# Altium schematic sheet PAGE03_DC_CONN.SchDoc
size B
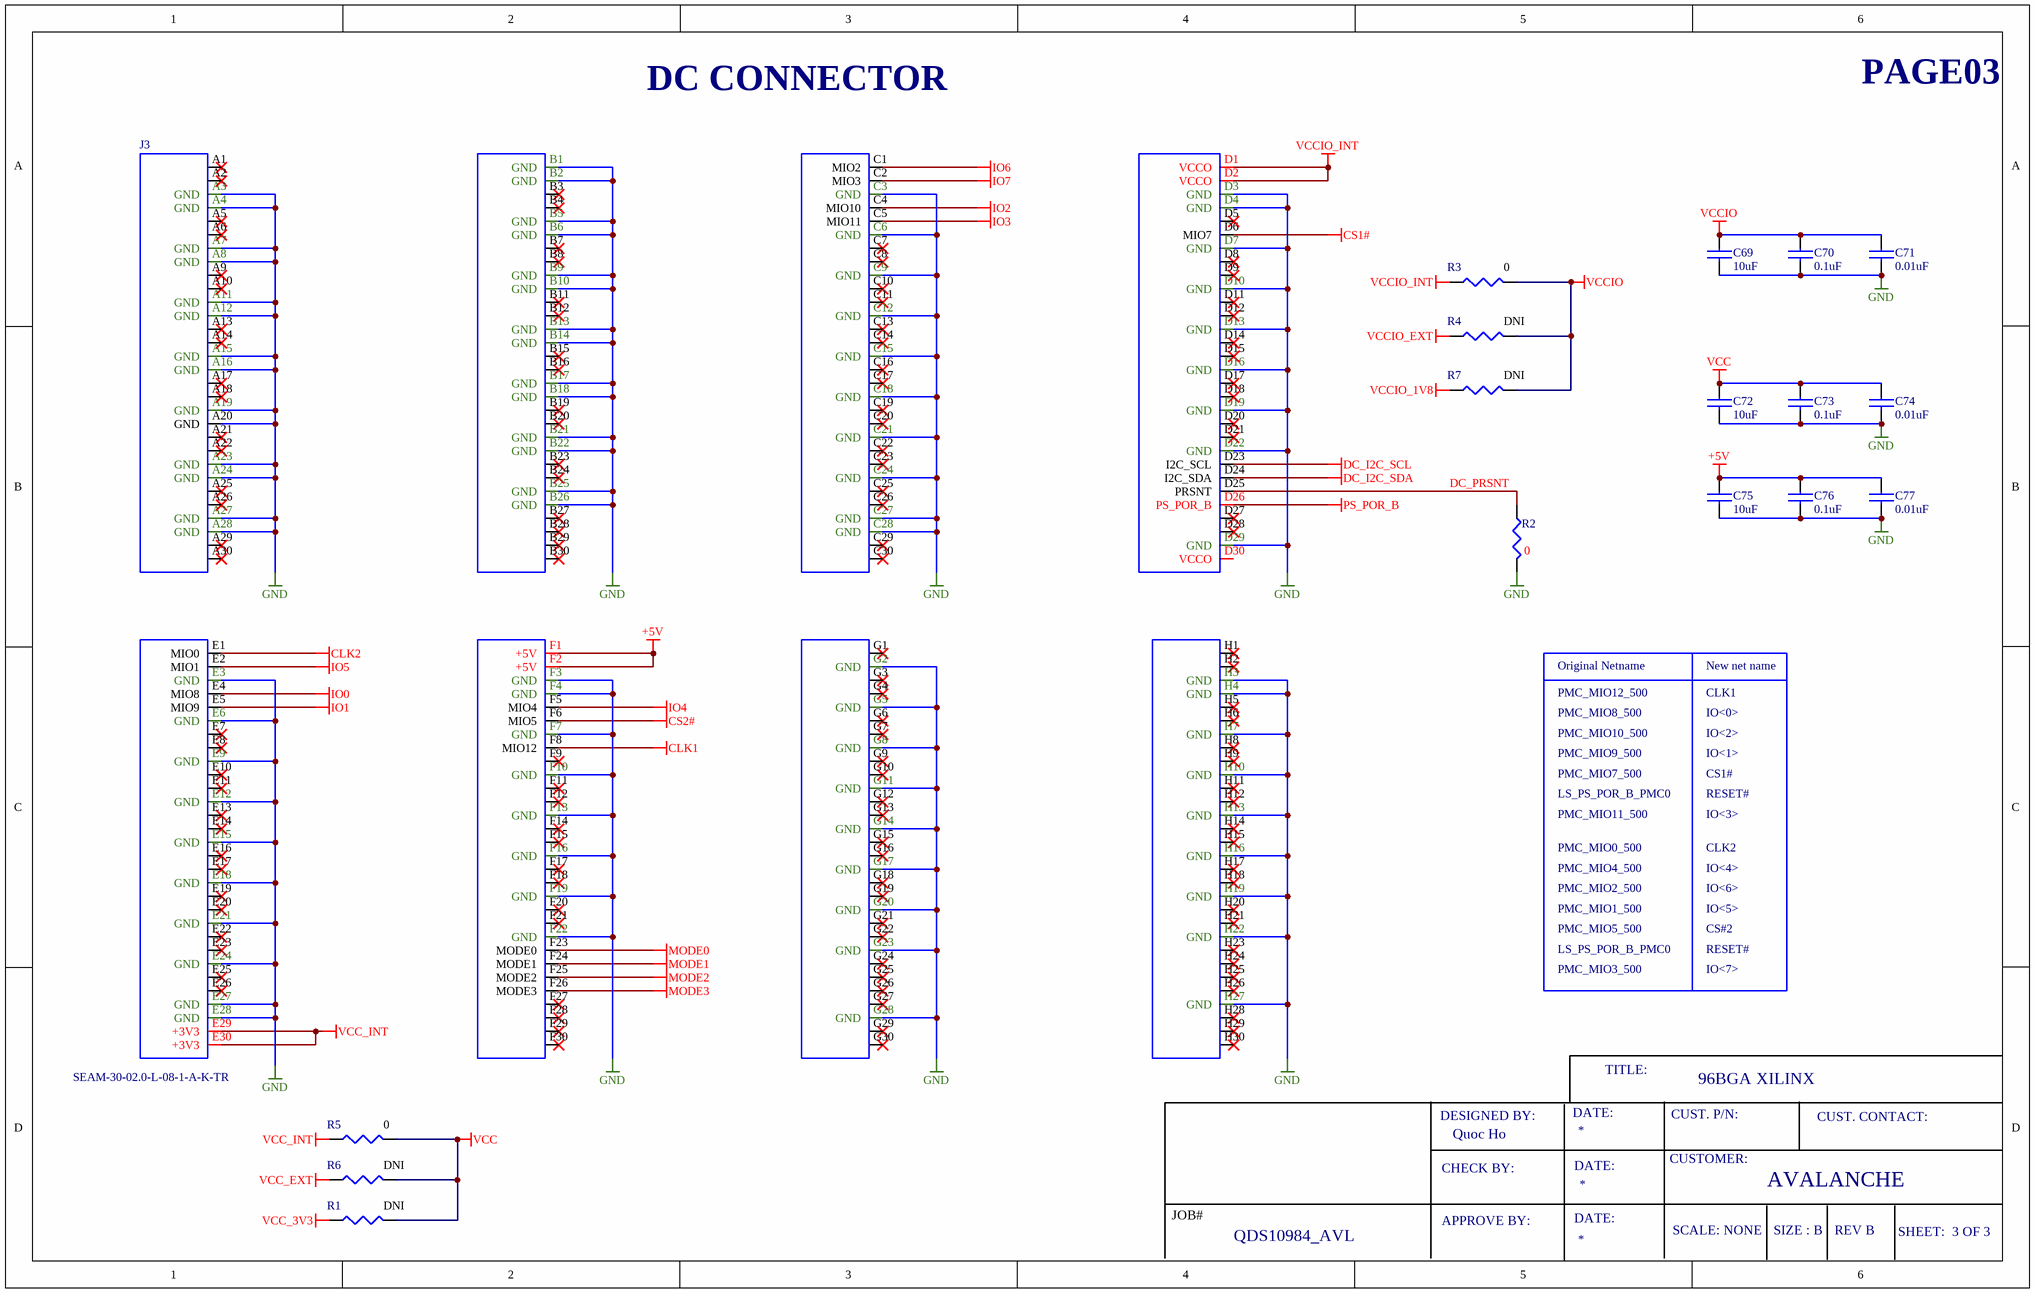
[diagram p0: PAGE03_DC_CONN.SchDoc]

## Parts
C69  10uF  [N_0603]
C70  0.1uF  [N_0603]
C71  0.01uF  [N_0603]
C72  10uF  [N_0603]
C73  0.1uF  [N_0603]
C74  0.01uF  [N_0603]
C75  10uF  [N_0603]
C76  0.1uF  [N_0603]
C77  0.01uF  [N_0603]
J3  SEAM-30-02.0-L-08-1-A-K-TR  [SAMTEC_SEAM-30-02.0-L-08-1-A-K-TR]
R1  DNI  [N_0603]
R2  0  [N_0603]
R3  0  [N_0603]
R4  DNI  [N_0603]
R5  0  [N_0603]
R6  DNI  [N_0603]
R7  DNI  [N_0603]

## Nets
+5V: C75.1 C76.1 C77.1 J3.F1(+5V) J3.F2(+5V)
CLK1: J3.F8(MIO12)
CLK2: J3.E1(MIO0)
CS1#: J3.D6(MIO7)
CS2#: J3.F6(MIO5)
DC_I2C_SCL: J3.D23(I2C_SCL)
DC_I2C_SDA: J3.D24(I2C_SDA)
GND: C69.2 C70.2 C71.2 C72.2 C73.2 C74.2 C75.2 C76.2 C77.2 J3.A3(GND) J3.A4(GND) J3.A7(GND) J3.A8(GND) J3.A11(GND) J3.A12(GND) J3.A15(GND) J3.A16(GND) J3.A19(GND) J3.A20(GND) J3.A23(GND) J3.A24(GND) J3.A27(GND) J3.A28(GND) J3.B1(GND) J3.B2(GND) J3.B5(GND) J3.B6(GND) J3.B9(GND) J3.B10(GND) J3.B13(GND) J3.B14(GND) J3.B17(GND) J3.B18(GND) J3.B21(GND) J3.B22(GND) J3.B25(GND) J3.B26(GND) J3.C3(GND) J3.C6(GND) J3.C9(GND) J3.C12(GND) J3.C15(GND) J3.C18(GND) J3.C21(GND) J3.C24(GND) J3.C27(GND) J3.C28(GND) J3.D3(GND) J3.D4(GND) J3.D7(GND) J3.D10(GND) J3.D13(GND) J3.D16(GND) J3.D19(GND) J3.D22(GND) J3.D29(GND) J3.E3(GND) J3.E6(GND) J3.E9(GND) J3.E12(GND) J3.E15(GND) J3.E18(GND) J3.E21(GND) J3.E24(GND) J3.E27(GND) J3.E28(GND) J3.F3(GND) J3.F4(GND) J3.F7(GND) J3.F10(GND) J3.F13(GND) J3.F16(GND) J3.F19(GND) J3.F22(GND) J3.G2(GND) J3.G5(GND) J3.G8(GND) J3.G11(GND) J3.G14(GND) J3.G17(GND) J3.G20(GND) J3.G23(GND) J3.G28(GND) J3.H3(GND) J3.H4(GND) J3.H7(GND) J3.H10(GND) J3.H13(GND) J3.H16(GND) J3.H19(GND) J3.H22(GND) J3.H27(GND) R2.2
IO0: J3.E4(MIO8)
IO1: J3.E5(MIO9)
IO2: J3.C4(MIO10)
IO3: J3.C5(MIO11)
IO4: J3.F5(MIO4)
IO5: J3.E2(MIO1)
IO6: J3.C1(MIO2)
IO7: J3.C2(MIO3)
MODE0: J3.F23(MODE0)
MODE1: J3.F24(MODE1)
MODE2: J3.F25(MODE2)
MODE3: J3.F26(MODE3)
PS_POR_B: J3.D26(PS_POR_B)
VCC: C72.1 C73.1 C74.1 R1.2 R5.2 R6.2
VCC_3V3: R1.1
VCC_EXT: R6.1
VCC_INT: J3.E29(+3V3) J3.E30(+3V3) R5.1
VCCIO: C69.1 C70.1 C71.1 R3.2 R4.2 R7.2
VCCIO_1V8: R7.1
VCCIO_EXT: R4.1
VCCIO_INT: J3.D1(VCCO) J3.D2(VCCO) R3.1
DC_PRSNT: J3.D25(PRSNT) R2.1

Not connected (* = marked no-connect by the designer): J3 A1* A2* A5* A6* A9* A10* A13* A14* A17* A18* A21* A22* A25* A26* A29* A30* B3* B4* B7* B8* B11* B12* B15* B16* B19* B20* B23* B24* B27* B28* B29* B30* C7* C8* C10* C11* C13* C14* C16* C17* C19* C20* C22* C23* C25* C26* C29* C30* D5* D8* D9* D11* D12* D14* D15* D17* D18* D20* D21* D27* D28* D30(VCCO) E7* E8* E10* E11* E13* E14* E16* E17* E19* E20* E22* E23* E25* E26* F9* F11* F12* F14* F15* F17* F18* F20* F21* F27* F28* F29* F30* G1* G3* G4* G6* G7* G9* G10* G12* G13* G15* G16* G18* G19* G21* G22* G24* G25* G26* G27* G29* G30* H1* H2* H5* H6* H8* H9* H11* H12* H14* H15* H17* H18* H20* H21* H23* H24* H25* H26* H28* H29* H30*

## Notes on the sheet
- DC CONNECTOR
- PAGE03
- PMC_MIO12_500
- Original Netname
- CLK1
- New net name
- PMC_MIO8_500
- PMC_MIO10_500
- PMC_MIO9_500
- PMC_MIO7_500
- IO<0>
- IO<2>
- IO<1>
- CS1#
- LS_PS_POR_B_PMC0
- PMC_MIO11_500
- RESET#
- IO<3>
- PMC_MIO0_500
- PMC_MIO4_500
- PMC_MIO2_500
- PMC_MIO1_500
- CLK2
- IO<4>
- IO<6>
- IO<5>
- PMC_MIO3_500
- PMC_MIO5_500
- IO<7>
- CS#2
- TITLE:
- 96BGA XILINX
- DESIGNED BY:
- CHECK BY:
- Quoc Ho
- DATE:
- CUSTOMER:
- CUST. P/N:
- CUST. CONTACT:
- JOB#
- QDS10984_AVL
- APPROVE BY:
- SCALE: NONE
- AVALANCHE
- SIZE : B
- REV B
- SHEET:  3 OF 3

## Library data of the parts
C69 C72 C75 = CAP: CAP CER 10UF 10V X5R 0603; Part Number: CL10A106MP8NNNC
C70 C73 C76 = CAP: CAP CER 0.1UF 16V X7R 0603; Part Number: CL10B104KO8NNNC
C71 C74 C77 = CAP: CAP CER  0.01UF 16V X7R 0603; Part Number: CL10B103KO8WPNC
J3 = SEAM-30-02.0-L-08-1-A-K-TR: CONN HD ARRAY PLUG 240P SMD GOLD
R1 R4 R6 R7 = RES
R2 R3 R5 = RES: RES 0 OHM JUMPER 1/10W 0603; Part Number: RC0603JR-070RL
